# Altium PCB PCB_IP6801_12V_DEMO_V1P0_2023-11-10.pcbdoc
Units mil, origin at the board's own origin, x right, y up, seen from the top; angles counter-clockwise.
Board outline 3537 x 2371 mil, 2 copper layers (Top Layer, Bottom Layer); 41 components, 32 nets, 127 pads, 103 vias.
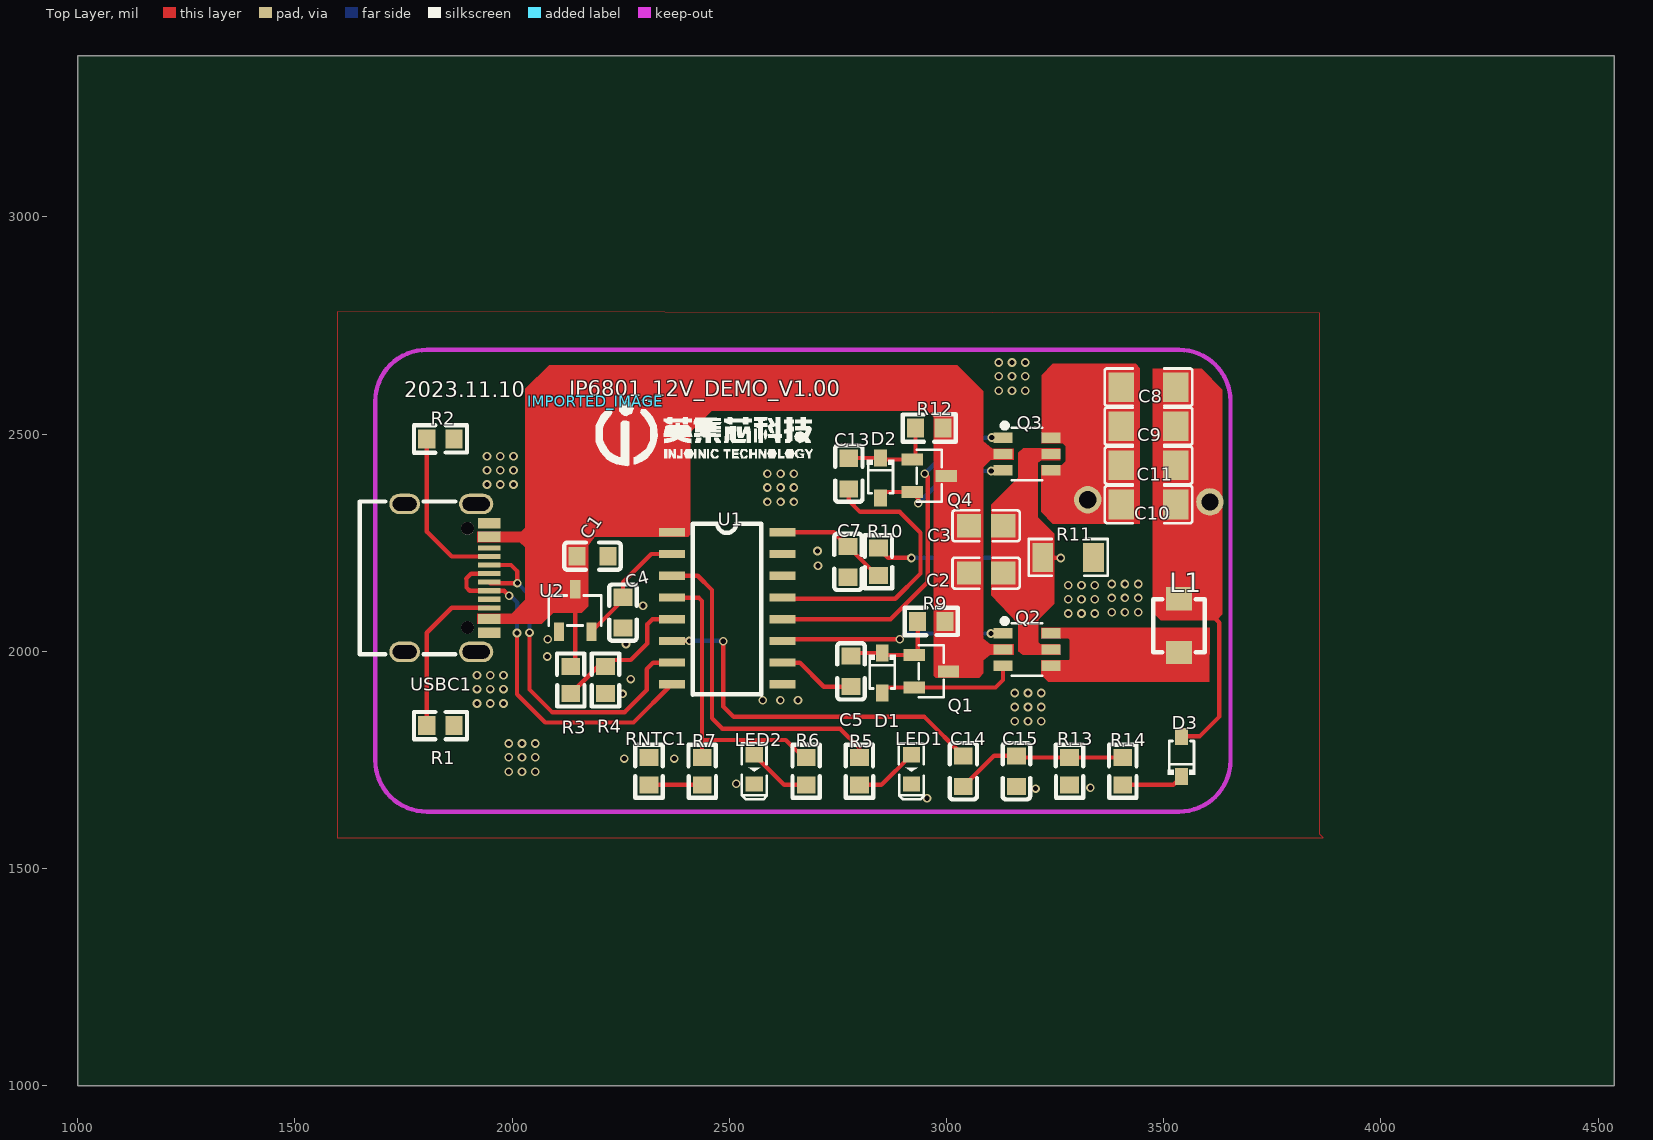
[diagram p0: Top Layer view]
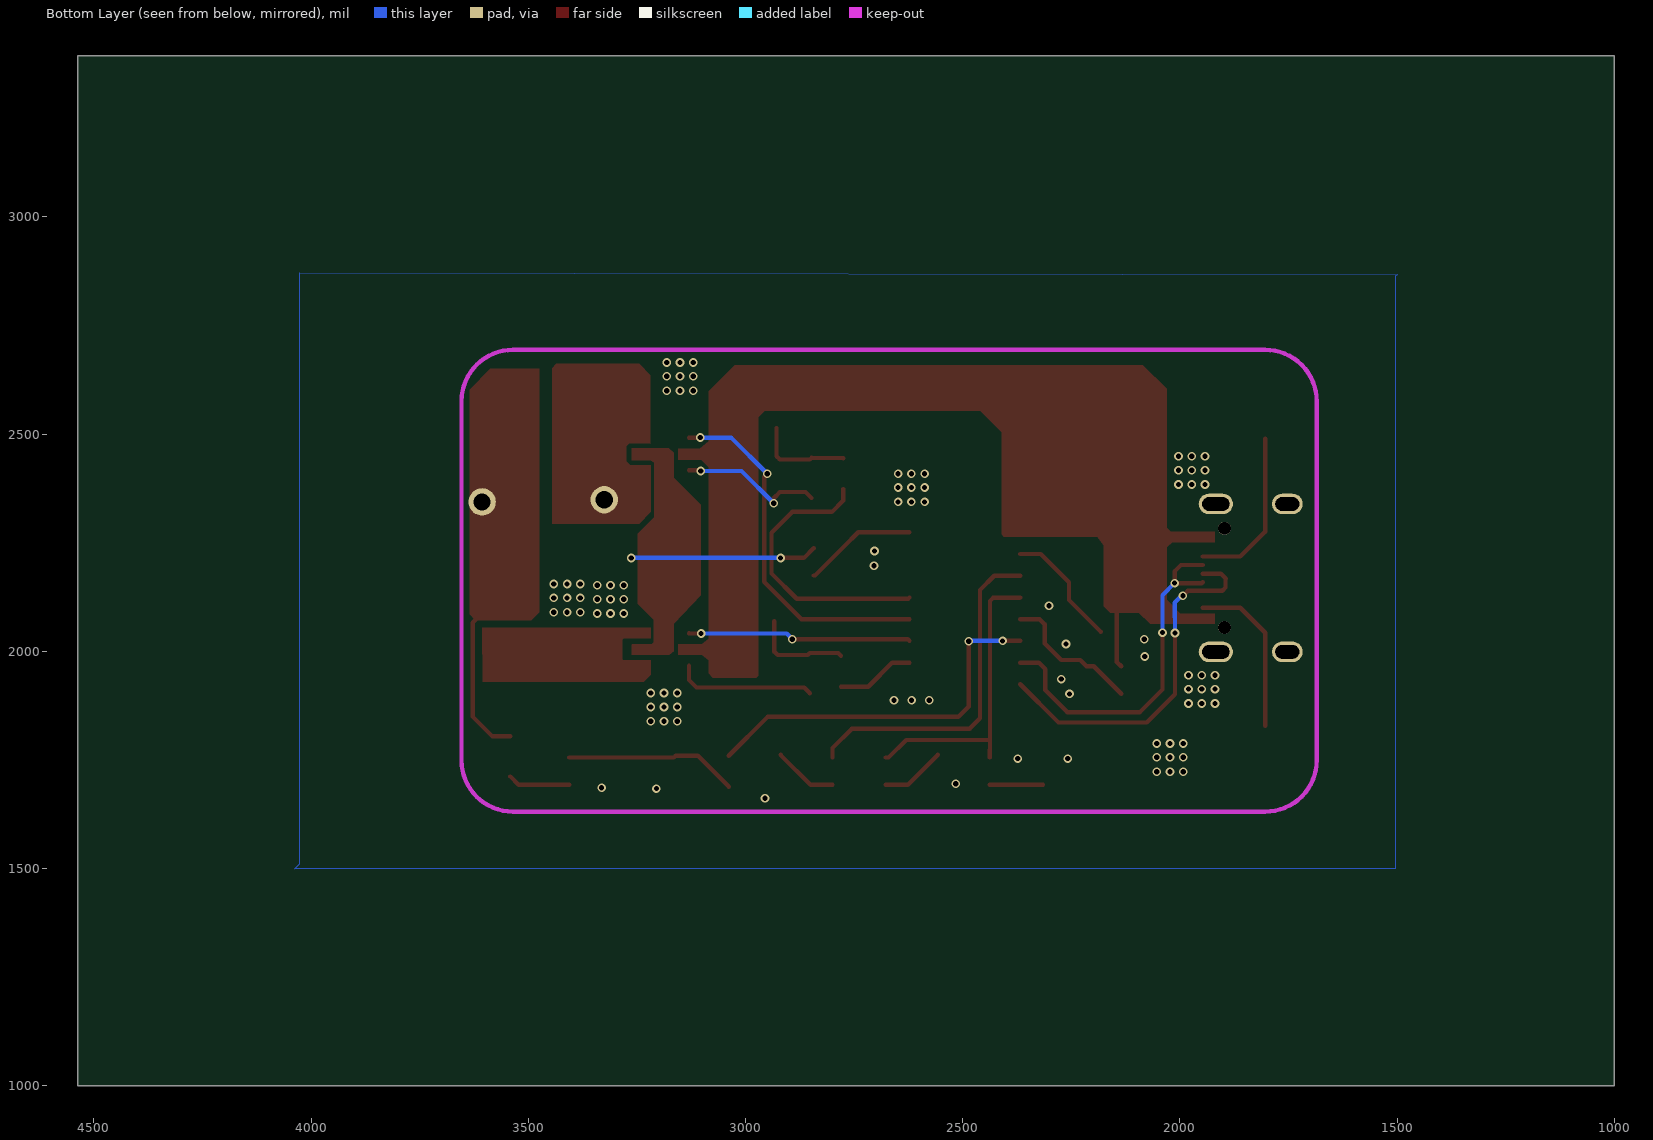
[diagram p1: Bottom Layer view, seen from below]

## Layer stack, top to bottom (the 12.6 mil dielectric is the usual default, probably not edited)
Top Layer: signal copper (thickness not stored)
Dielectric: dielectric 12.6, FR-4, Dk 4.8
Bottom Layer: signal copper (thickness not stored)

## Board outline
4537,1000 1000,1000 1000,3371 4537,3371

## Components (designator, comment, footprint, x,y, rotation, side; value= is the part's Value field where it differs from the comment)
C1 "4.7uF" C0603 2185,2219 r0 top
C2 "22uF" C0805 3091,2180 r180 top
C3 "22uF" C0805 3091,2289 r180 top
C4 "4.7uF" C0603 2255,2089 r90 top
C5 "100nF" C0603 2780,1954 r90 top
C7 "10nF" C0603 2773,2206 r90 top
C8 "100nF" C1206 3465,2608 r180 top
C9 "100nF" C1206 3465,2518 r180 top
C10 "100nF" C1206 3465,2338 r180 top
C11 "100nF" C1206 3465,2428 r180 top
C13 "100nF" C0603 2775,2409 r90 top
C14 "10nF" C0603 3038.49,1724 r270 top
C15 "10nF" C0603 3160.77,1724 r90 top
D1 "1N4148WS" SOD-323_L1.8-W1.3-LS2.5-RD 2852,1950 r270 top
D2 "1N4148WS" SOD-323_L1.8-W1.3-LS2.5-RD 2848,2399 r270 top
D3 "1N4148WS" SOD-323_L1.8-W1.3-LS2.5-RD 3541,1758 r90 top
IMPORTED_IMAGE "IMPORTED_IMAGE" IMPORTED_IMAGE 2191.96,2576.04 r0 top
L1 "6.3uH" IND-SMD_L4.5-W3.0 3535,2059 r90 top
LED1 "LED" LED0603_GREEN 2918.96,1728.13 r270 top
LED2 "LED" LED0603_RED 2557.22,1728.13 r270 top
Q1 "MMBT3904" SOT-23-3_L2.9-W1.3-P0.95-LS2.4-BR 2965,1954 r180 top
Q2 "AP10G02LI" SOT-23-6_L2.9-W1.6-P0.95-LS2.7-BL 3185,2004 r270 top
Q3 "AP10G02LI" SOT-23-6_L2.9-W1.6-P0.95-LS2.7-BL 3185,2454 r270 top
Q4 "MMBT3904" SOT-23-3_L2.9-W1.3-P0.95-LS2.4-BR 2960,2404 r180 top
R1 "5.1k" R0603 1835,1829 r180 top
R2 "5.1k" R0603 1835,2489 r180 top
R3 "33k" R0603 2135,1934 r90 top
R4 "11k" R0603 2215,1934 r90 top
R5 "1k" R0603 2799.43,1723.99 r90 top
R6 "1k" R0603 2676.95,1723.99 r90 top
R7 "3.3k" R0603 2437.49,1724.01 r270 top
R9 "1k" R0603 2965,2069 r180 top
R10 "3.3k" R0603 2843,2206 r270 top
R11 "20mR" R1206 3280,2216 r0 top
R12 "1k" R0603 2960,2514 r180 top
R13 "33k" R0603 3283.26,1723.99 r90 top
R14 "3.3k" R0603 3405.54,1724.01 r270 top
RNTC1 "10k" R0603 2315,1724.01 r270 top
U1 "IP6801" SOP16L 2495.01,2098.99 r0 top
U2 "LR8321A-T50" SOT-23-3_L2.9-W1.6-P1.90-LS2.8-BR 2145.01,2094 r270 top
USBC1 "TYPE-C-31-M-12" USB-C_SMD-TYPE-C-31-M-12 1850,2169 r270 top

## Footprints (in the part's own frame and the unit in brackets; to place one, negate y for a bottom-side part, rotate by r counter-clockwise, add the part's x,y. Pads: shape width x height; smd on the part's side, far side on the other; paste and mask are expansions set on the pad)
C0603 [mm]
  rect 1x1.1 smd paste+0 mask+0.102: 1(-0.9,0) 2(0.9,0)
  silkscreen extent -1.65,-0.8 1.65,0.8
C0805 [mm]
  rect 1.41x1.35 smd paste-100 mask+0.051: 1(-1,0) 2(1,0)
  silkscreen extent -1.96,-0.9 1.96,0.9
C1206 [mm]
  rect 1.485x1.728 smd paste-100 mask+0.051: 1(-1.593,0) 2(1.593,0)
  silkscreen extent -2.56,-1.09 2.56,1.09
IMPORTED_IMAGE [mil]
  silkscreen extent 0,-150 500,0
IND-SMD_L4.5-W3.0 [mm]
  rect 1.35x1.5 smd paste+0 mask+0.05: 1(-1.575,0) 2(1.575,0)
  silkscreen extent -1.55,-1.5 1.55,1.5
LED0603_GREEN [mm]
  rect 0.9x1 smd paste+0 mask+0.051: 1(-0.85,0) 2(0.85,0)
  silkscreen extent -1.54,-0.73 1.75,0.73
LED0603_RED [mm]
  rect 0.9x1 smd paste+0 mask+0.051: 1(-0.85,0) 2(0.85,0)
  silkscreen extent -1.54,-0.73 1.75,0.73
R0603 [mm]
  rect 1x1.1 smd paste+0 mask+0.102: 1(-0.8,0) 2(0.8,0)
  silkscreen extent -1.55,-0.8 1.55,0.81
R1206 [mil]
  rect 47.54x66.97 smd paste-3937.01 mask+2: 1(-58.22,0) 2(58.22,0)
  silkscreen extent -91,-42 91,42
SOD-323_L1.8-W1.3-LS2.5-RD [mm]
  rect 1x0.75 smd paste+0 mask+0.051: 1(-1.173,0) 2(1.173,0)
  silkscreen extent -1.08,-0.8 0.9,0.8
SOP16L [mm]
  rect 1.52x0.48 smd paste+0 mask+0.051: 1(-3.238,4.445) 2(-3.238,3.175) 3(-3.238,1.905) 4(-3.239,0.635) 5(-3.239,-0.635) 6(-3.239,-1.905) 7(-3.239,-3.175) 8(-3.239,-4.445) 9(3.238,-4.445) 10(3.238,-3.175) 11(3.238,-1.905) 12(3.238,-0.635) 13(3.238,0.635) 14(3.238,1.905) 15(3.238,3.175) 16(3.239,4.445)
  silkscreen extent -2.02,-5.05 1.99,4.95
SOT-23-3_L2.9-W1.3-P0.95-LS2.4-BR [mm]
  rect 1.25x0.7 smd paste+0 mask+0.051: 1(1,-0.95) 2(1,0.95) 3(-1,0)
  silkscreen extent -0.73,-1.53 0.73,1.53
SOT-23-3_L2.9-W1.6-P1.90-LS2.8-BR [mm]
  rect 1.07x0.6 smd paste+0 mask+0.051: 1(1.235,-0.95) 2(1.235,0.95) 3(-1.235,0)
  silkscreen extent -0.88,-1.54 0.88,1.54
SOT-23-6_L2.9-W1.6-P0.95-LS2.7-BL [mm]
  rect 0.6x1.1 smd paste+0 mask+0.051: 1(-0.95,-1.4) 2(0,-1.4) 3(0.95,-1.4) 4(0.95,1.4) 5(0,1.4) 6(-0.95,1.4)
  silkscreen extent -1.82,-1.45 1.54,0.89
USB-C_SMD-TYPE-C-31-M-12 [mm]
  oval 1.2x2 hole 0.8 slot 1.6 at 90 deg paste+0 mask+0.051: 0(-4.325,1.706) 1(4.325,1.706)
  oval 1.2x1.8 hole 0.8 slot 1.4 at 90 deg paste+0 mask+0.051: 2(4.325,-2.474) 3(-4.325,-2.474)
  rect 0.3x1.3 smd paste-100 mask+0.051: A1(-3.35,2.474) A4(-2.55,2.474) A5(-1.25,2.474) A6(-0.25,2.474) A7(0.25,2.474) A8(1.25,2.474) A9(2.55,2.474) A12(3.35,2.474) B1(3.05,2.474) B4(2.25,2.474) B5(1.75,2.474) B6(0.75,2.474) B7(-0.75,2.474) B8(-1.75,2.474) B9(-2.25,2.474) B12(-3.05,2.474)
  round 0.75 hole 0.75 unplated paste+0: ""(-2.9,1.206) ""(2.9,1.206)
  silkscreen extent -4.47,-5.09 4.47,0.49

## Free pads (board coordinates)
  round 62.99 hole 39.37 paste+0 mask+2: 1(3325,2349) 2(3606,2344)

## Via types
v1: diameter 20, hole 12, Top Layer to Bottom Layer, tented both sides, 103 vias

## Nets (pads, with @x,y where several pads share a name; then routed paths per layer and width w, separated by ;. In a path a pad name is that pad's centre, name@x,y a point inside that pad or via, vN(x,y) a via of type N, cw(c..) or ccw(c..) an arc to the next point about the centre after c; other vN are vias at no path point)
C5_2: C5.2 D1.1 Q1.1 R9.2 | length 231.3
  Top Layer w10: C5.2 2786.72,1996.16 D1.1 2856.76,1991.4 Q1.1 2933.5,1999.28 R9.2
C10_2: C8.2 C9.2 C10.2 C11.2 pad.1 Q3.4 Q3.6
C13_2: C13.2 D2.1 Q4.1 R12.2 | length 223.1
  Top Layer w10: C13.2 D2.1 ; D2.1 2851.76,2441.4 Q4.1 2928.5,2449.28 R12.2
CC1: R1.2 USBC1.B5 | length 381.3
  Top Layer w10: R1.2 1803.5,2042.5 1861.1,2100.1 USBC1.B5
CC2: R2.2 USBC1.A5 | length 381.1
  Top Layer w10: R2.2 1803.5,2275.5 1860.79,2218.21 USBC1.A5
DM: U1.7 USBC1.A7 USBC1.B7 | length 844.1
  Top Layer w10: USBC1.A7 1949.57,2157 v1(2012,2157) 2012,2184 1997.47,2198.53 USBC1.B7 ; v1(2040,2043) 2040,1912 2092,1860 2259,1860 2310,1911 2310,1959 2325.01,1974.02 U1.7
  Bottom Layer w10: v1(2012,2157) 2040,2129 v1(2040,2043)
DP: U1.8 USBC1.A6 USBC1.B6 | length 841.1
  Top Layer w10: USBC1.A6 1905.84,2178.84 1894,2167 1895,2166 1895,2147 1902.53,2139.47 USBC1.B6 1981.53,2139.47 v1(1993,2128) ; v1(2011,2042) 2011,1901 2076,1836 2279.47,1836 U1.8
  Bottom Layer w10: v1(1993,2128) 1996,2128 2012,2112 v1(2011,2042)
DRV1H: C5.1 U1.10 | length 180.4
  Top Layer w10: U1.10 2662,1974 2717.4,1918.6 C5.1
DRV1L: Q2.1 U1.11 | length 514.6
  Top Layer w10: U1.11 2626.49,2028 v1(2892,2028) ; v1(3102,2041) 3129.5,2041 Q2.1
  Bottom Layer w10: v1(2892,2028) 2905,2041 v1(3102,2041)
DRV2H: C13.1 U1.13 | length 659
  Top Layer w10: U1.13 2625.5,2121 2882,2121 2940,2179 2940,2273 2892,2321 2801,2321 2775,2347 C13.1
DRV2L: Q3.1 U1.12 | length 836.3
  Top Layer w10: U1.12 2871,2074 2957,2160 2957,2402 v1(2950,2409) ; v1(3104,2492) Q3.1
  Bottom Layer w10: v1(2950,2409) 3033,2492 v1(3104,2492)
GND: C1.2 C4.1 C7.1 C15.1 LED1.2 LED2.2 R1.1 R2.1 R4.1 R11.2 R13.1 RNTC1.1 U1.9 U1.15 U2.1 USBC1.0 USBC1.A1 USBC1.A12 USBC1.B1 USBC1.B12
  other v1: 2955,1662 3205,1684 3331,1686 2516,1695 1992,1723 2022.5,1723 2053,1723 2258,1753 2373,1753 1992,1756 2022.5,1756 2053,1756 1992,1788 2022.5,1788 2053,1788 3157,1839 3187.5,1839 3218,1839 3157,1872 3187.5,1872 3218,1872 1919,1880 1949.5,1880 1980,1880 2577,1887.5 2617.5,1887.5 2658,1887.5 2254,1902 3157,1904 3187.5,1904 3218,1904 1919,1913 1949.5,1913 1980,1913 2273,1936 1919,1945 1949.5,1945 1980,1945 2081,1988 2262,2017 2082,2028 3280,2087 3310.5,2087 3341,2087 3380,2090 3410.5,2090 3441,2090 2301,2105 3280,2120 3310.5,2120 3341,2120 3380,2123 3410.5,2123 3441,2123 3280,2152 3310.5,2152 3341,2152 3380,2155 3410.5,2155 3441,2155 2704,2197 2703,2231 2587.5,2344 2618,2344 2648.5,2344 2587.5,2377 2618,2377 2648.5,2377 1942,2384 1972.5,2384 2003,2384 2587.5,2409 2618,2409 2648.5,2409 1942,2417 1972.5,2417 2003,2417 1942,2449 1972.5,2449 2003,2449 3120,2600 3150.5,2600 3181,2600 3120,2633 3150.5,2633 3181,2633 3120,2665 3150.5,2665 3181,2665
ISNS: C7.2 R10.2 U1.16 | length 261.7
  Top Layer w10: U1.16 2740.44,2273.99 C7.2 2839.94,2174.5 R10.2
L1_1: L1.1 Q2.4 Q2.6
LED1: R5.2 U1.3 | length 791
  Top Layer w10: U1.3 2427,2174 2460,2141 2460,1846 2484,1822 2755,1822 2799.4,1777.6 R5.2
LED2: R6.2 R7.1 U1.4 | length 694.3
  Top Layer w10: U1.4 2368.51,2123 2430,2123 2437.05,2115.95 2437.05,1791.78 ; R7.1 2437,1796 2630,1796 2670.5,1755.5 R6.2
PGND: C2.1 C3.1 Q2.5 Q3.5 R10.1 R11.1 | length 470.9
  Top Layer w10: R10.1 2865.49,2215 v1(2919,2215) ; R11.1 3222.78,2215 v1(3263,2215)
  Bottom Layer w10: v1(2919,2215) v1(3263,2215)
Q2_3: D1.2 Q1.2 Q2.3 | length 323.1
  Top Layer w10: D1.2 2864.76,1916.6 Q1.2 3112.6,1916.6 3129.88,1933.88 Q2.3
Q3_3: D2.2 Q3.3 Q4.2 | length 336.1
  Top Layer w10: D2.2 2861.76,2366.6 Q4.2 ; Q4.2 2935,2352.22 v1(2935,2341) ; v1(3103,2415) 3104.6,2416.6 Q3.3
  Bottom Layer w10: v1(2935,2341) 3009,2415 v1(3103,2415)
R5_1: LED1.1 R5.1 | length 148.2
  Top Layer w10: R5.1 2849.85,1692.49 LED1.1
R6_1: LED2.1 R6.1 | length 148.4
  Top Layer w10: LED2.1 2626.33,1692.49 R6.1
R7_2: R7.2 RNTC1.2 | length 122.5
  Top Layer w10: RNTC1.2 R7.2
R14_1: C14.2 C15.2 R13.2 R14.1 | length 398
  Top Layer w10: C14.2 3109.37,1759.44 C15.2 3164.73,1755.48 R13.2 ; R13.2 R14.1
R14_2: D3.1 R14.2 | length 143.5
  Top Layer w10: R14.2 3521.7,1692.5 D3.1
U1_14: U1.14
USBC1_A8: USBC1.A8
USBC1_B8: USBC1.B8
VBUS: C1.1 C2.2 C3.2 Q1.3 Q2.2 Q3.2 Q4.3 R3.2 R9.1 R12.1 U1.1 U2.3 USBC1.A4 USBC1.A9 USBC1.B4 USBC1.B9 | length 181.3
  Top Layer w10: R3.2 2145,1975.5 U2.3
VC: C8.1 C9.1 C10.1 C11.1 D3.2 L1.2 pad.2 | length 437.8
  Top Layer w10: L1.2 3573,2121 3628,2066 3628,1850 3582.16,1804.16 D3.2
VCC: C4.2 U1.2 U2.2 | length 283.1
  Top Layer w10: U2.2 2255,2117.97 C4.2 2255,2159 2320,2224 U1.2
VDEM: C14.1 U1.6 | length 868.5
  Top Layer w10: U1.6 v1(2408,2024) ; v1(2486,2023) 2486,1873 2510,1849 2948.9,1849 C14.1
  Bottom Layer w10: v1(2408,2024) 2485,2024 v1(2486,2023)
VSNS: R3.1 R4.2 U1.5 | length 329.3
  Top Layer w10: R3.1 2197.99,1965.5 R4.2 2229.5,1980 2273,1980 2311,2018 2311,2062 2323.01,2074.01 U1.5
pads on no net: USBC1. USBC1.1 USBC1.2 USBC1.3

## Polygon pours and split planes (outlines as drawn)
GND on Bottom Layer (solid): 1500,2867 1504,2863 1504,1500 4037,1500 4026,1511 4026,2871
GND on Top Layer (solid): 1597,2782 1597,1571 3867,1571 3859,1579 3859,2778

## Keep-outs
Keep-Out Layer:
  lines w10: 1685,1749.12 ccw(c1803.11,1749.12) 1803.11,1631.01 ; 1685,2575.89 cw(c1803.11,2575.89) 1803.11,2694 ; 3535.39,1631.01 ccw(c3535.39,1749.12) 3653.5,1749.12 ; 3535.39,2694 cw(c3535.39,2575.89) 3653.5,2575.89

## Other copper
Top Layer:
  region net VBUS: 1920,2063 2068,2063 2095,2089 2160,2089 2175,2104 2175,2244 2190,2264 2405,2264 2410,2269 2410,2504 2460,2554 2955,2554 2970,2539 2970,1944 2975,1939 3075,1939 3085,1949 3085,1979 3100,1992 3155,1992 3155,2016 3100,2016 3085,2029 3085,2424 3102,2441 3155,2441 3155,2466 3105,2466 3085,2484 3085,2599 3025,2659 2085,2659 2030,2604 2030,2284 2021,2275 1920,2275 1920,2251 2017,2251 2030,2239 2030,2119 1999,2086 1920,2086
  region net C10_2: 3445,2294 3445,2652 3435,2662 3245,2662 3219,2636 3219,2480 3218,2479 3267,2479 3274,2472 3274,2437 3265,2428 3218,2428 3218,2321 3245,2294
  region net VC: 3475,2651 3475,2090 3493,2072 3622,2072 3635,2085 3635,2602 3634,2603 3587,2650
  region net L1_1: 3218,2054 3218,2030 3280,2030 3283,2027 3283,1982 3280,1979 3218,1979 3218,1946 3234,1930 3605,1930 3606,2054
  region net PGND: 3262,2467 3176,2467 3165,2457 3165,2400 3103,2337 3103,2129 3165,2063 3165,2000 3175,1992 3262,1992 3262,2015 3261,2016 3216,2016 3211,2021 3211,2073 3248,2110 3248,2271 3210,2309 3210,2434 3218,2440 3262,2440

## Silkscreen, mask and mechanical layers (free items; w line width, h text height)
Top Overlay:
  text "IP6801_12V_DEMO_V1.00" at 2132,2587.5 h35
  text "2023.11.10" at 1752,2584.5 h35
